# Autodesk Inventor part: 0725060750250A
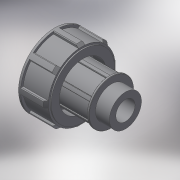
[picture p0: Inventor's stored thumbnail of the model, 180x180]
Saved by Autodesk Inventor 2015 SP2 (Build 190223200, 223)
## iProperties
Created: 2017-04
Part Number: 0725060750250A
Material: Generic
Description: PLASSON THREADED ADAPTOR 75-2.1/2"
Document SubType Name: Modeling
Designer: KIM
Density: 1 g/cm^3
Appearance: Default
Author: KIM
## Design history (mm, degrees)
derived "07250.ipt"
feature "Solid1::07250.ipt"
tag "TaggingFeature1"
body "Solid1"
other parameters: "d1" = 75.184, "d2" = 134, "d3" = 29, "d6" = 134, "d7" = 124.62, "d8" = 107.2, "d9" = 75, "d10" = 90.2208, "d12" = 45.1104, "d13" = 60.1472, "d14" = 33.35, "d15" = 100.5, "d16" = 4.02, "d17" = 53.6, "d18" = 29, "d19" = 34.8, "d24" = 15.0368, "d25" = 7.5184, "d27" = 0, "d28" = 6.01472, "d31" = 1.50368, "d35" = 360 deg, "d41" = 29.337, "d56" = 82.5, "d57" = 7.5, "d58" = 3.75, "d60" = 0, "d61" = 0.75184, "d64" = 0.75184, "d68" = 360 deg, "d_" = 75, "R_" = 75.184, "E_" = 134, "H_" = 134, "l_2" = 29, "d55" = 75
